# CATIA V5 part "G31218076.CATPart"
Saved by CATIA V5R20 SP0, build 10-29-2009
Part number: G31218076
Revision: 8
Definition: design
Nomenclature: G31218076
Source: made
Description: NOT SPECIFIED
Bounding box of the stored display mesh (mm): x -8 to 76, y -15.5 to 15.5, z -15.5 to 15.5
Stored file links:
  C:\Users\Raffaele\Desktop\3D X SITO CF\BOLEX\23-BUSH REF 312\G31218076.CATPart

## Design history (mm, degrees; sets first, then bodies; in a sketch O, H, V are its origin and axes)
Body1 "MANIFOLD_SOLID_BREP #19379" (main body)
  Solid1: solid without history
Body2 "MANIFOLD_SOLID_BREP #19526"
  Solid2: solid without history
Body3 "MANIFOLD_SOLID_BREP #19673"
  Solid3: solid without history
Body4 "MANIFOLD_SOLID_BREP #19820"
  Solid4: solid without history
Body5 "MANIFOLD_SOLID_BREP #19967"
  Solid5: solid without history
Body6 "MANIFOLD_SOLID_BREP #20116"
  Solid6: solid without history
Body7 "MANIFOLD_SOLID_BREP #20265"
  Solid7: solid without history
Body8 "MANIFOLD_SOLID_BREP #20414"
  Solid8: solid without history
Body9 "MANIFOLD_SOLID_BREP #20563"
  Solid9: solid without history
Body10 "MANIFOLD_SOLID_BREP #20712"
  Solid10: solid without history
Body11 "MANIFOLD_SOLID_BREP #20861"
  Solid11: solid without history
Body12 "MANIFOLD_SOLID_BREP #21010"
  Solid12: solid without history
Body13 "MANIFOLD_SOLID_BREP #21159"
  Solid13: solid without history
Body14 "MANIFOLD_SOLID_BREP #21308"
  Solid14: solid without history
Body15 "MANIFOLD_SOLID_BREP #21457"
  Solid15: solid without history
Body16 "MANIFOLD_SOLID_BREP #21606"
  Solid16: solid without history
Body17 "MANIFOLD_SOLID_BREP #21755"
  Solid17: solid without history
Body18 "MANIFOLD_SOLID_BREP #21904"
  Solid18: solid without history
Body19 "MANIFOLD_SOLID_BREP #22053"
  Solid19: solid without history
Body20 "MANIFOLD_SOLID_BREP #22202"
  Solid20: solid without history
Body21 "MANIFOLD_SOLID_BREP #22351"
  Solid21: solid without history
Body22 "MANIFOLD_SOLID_BREP #22500"
  Solid22: solid without history
Body23 "MANIFOLD_SOLID_BREP #22649"
  Solid23: solid without history
Body24 "MANIFOLD_SOLID_BREP #22798"
  Solid24: solid without history
Body25 "MANIFOLD_SOLID_BREP #22947"
  Solid25: solid without history
Body26 "MANIFOLD_SOLID_BREP #23096"
  Solid26: solid without history
Body27 "MANIFOLD_SOLID_BREP #23245"
  Solid27: solid without history
Body28 "MANIFOLD_SOLID_BREP #23394"
  Solid28: solid without history
Body29 "MANIFOLD_SOLID_BREP #23543"
  Solid29: solid without history
Body30 "MANIFOLD_SOLID_BREP #23692"
  Solid30: solid without history
Body31 "MANIFOLD_SOLID_BREP #23841"
  Solid31: solid without history
Body32 "MANIFOLD_SOLID_BREP #23988"
  Solid32: solid without history
Body33 "MANIFOLD_SOLID_BREP #24135"
  Solid33: solid without history
Body34 "MANIFOLD_SOLID_BREP #24284"
  Solid34: solid without history
Body35 "MANIFOLD_SOLID_BREP #24433"
  Solid35: solid without history
Body36 "MANIFOLD_SOLID_BREP #24582"
  Solid36: solid without history
Body37 "MANIFOLD_SOLID_BREP #24731"
  Solid37: solid without history
Body38 "MANIFOLD_SOLID_BREP #24880"
  Solid38: solid without history
Body39 "MANIFOLD_SOLID_BREP #25029"
  Solid39: solid without history
Body40 "MANIFOLD_SOLID_BREP #25178"
  Solid40: solid without history
Body41 "MANIFOLD_SOLID_BREP #25327"
  Solid41: solid without history
Body42 "MANIFOLD_SOLID_BREP #25476"
  Solid42: solid without history
Body43 "MANIFOLD_SOLID_BREP #25625"
  Solid43: solid without history
Body44 "MANIFOLD_SOLID_BREP #25774"
  Solid44: solid without history
Body45 "MANIFOLD_SOLID_BREP #25923"
  Solid45: solid without history
Body46 "MANIFOLD_SOLID_BREP #26072"
  Solid46: solid without history
Body47 "MANIFOLD_SOLID_BREP #26221"
  Solid47: solid without history
Body48 "MANIFOLD_SOLID_BREP #26370"
  Solid48: solid without history
Body49 "MANIFOLD_SOLID_BREP #26519"
  Solid49: solid without history
Body50 "MANIFOLD_SOLID_BREP #26668"
  Solid50: solid without history
Body51 "MANIFOLD_SOLID_BREP #26817"
  Solid51: solid without history
Body52 "MANIFOLD_SOLID_BREP #26966"
  Solid52: solid without history
Body53 "MANIFOLD_SOLID_BREP #27115"
  Solid53: solid without history
Body54 "MANIFOLD_SOLID_BREP #27264"
  Solid54: solid without history
Body55 "MANIFOLD_SOLID_BREP #27413"
  Solid55: solid without history
Body56 "MANIFOLD_SOLID_BREP #27560"
  Solid56: solid without history
Body57 "MANIFOLD_SOLID_BREP #27707"
  Solid57: solid without history
Body58 "MANIFOLD_SOLID_BREP #27856"
  Solid58: solid without history
Body59 "MANIFOLD_SOLID_BREP #28005"
  Solid59: solid without history
Body60 "MANIFOLD_SOLID_BREP #28154"
  Solid60: solid without history
Body61 "MANIFOLD_SOLID_BREP #28303"
  Solid61: solid without history
Body62 "MANIFOLD_SOLID_BREP #28452"
  Solid62: solid without history
Body63 "MANIFOLD_SOLID_BREP #28601"
  Solid63: solid without history
Body64 "MANIFOLD_SOLID_BREP #28748"
  Solid64: solid without history
Body65 "MANIFOLD_SOLID_BREP #28895"
  Solid65: solid without history
Body66 "MANIFOLD_SOLID_BREP #29044"
  Solid66: solid without history
Body67 "MANIFOLD_SOLID_BREP #29193"
  Solid67: solid without history
Body68 "MANIFOLD_SOLID_BREP #29342"
  Solid68: solid without history
Body69 "MANIFOLD_SOLID_BREP #29491"
  Solid69: solid without history
Body70 "MANIFOLD_SOLID_BREP #29640"
  Solid70: solid without history
Body71 "MANIFOLD_SOLID_BREP #29789"
  Solid71: solid without history
Body72 "MANIFOLD_SOLID_BREP #29938"
  Solid72: solid without history
Body73 "MANIFOLD_SOLID_BREP #30087"
  Solid73: solid without history
Body74 "MANIFOLD_SOLID_BREP #30236"
  Solid74: solid without history
Body75 "MANIFOLD_SOLID_BREP #30385"
  Solid75: solid without history
Body76 "MANIFOLD_SOLID_BREP #30534"
  Solid76: solid without history
Body77 "MANIFOLD_SOLID_BREP #30683"
  Solid77: solid without history
Body78 "MANIFOLD_SOLID_BREP #30832"
  Solid78: solid without history
Body79 "MANIFOLD_SOLID_BREP #30981"
  Solid79: solid without history
Body80 "MANIFOLD_SOLID_BREP #31130"
  Solid80: solid without history
Body81 "MANIFOLD_SOLID_BREP #31279"
  Solid81: solid without history
Body82 "MANIFOLD_SOLID_BREP #31428"
  Solid82: solid without history
Body83 "MANIFOLD_SOLID_BREP #31577"
  Solid83: solid without history
Body84 "MANIFOLD_SOLID_BREP #31726"
  Solid84: solid without history
Body85 "MANIFOLD_SOLID_BREP #31875"
  Solid85: solid without history
Body86 "MANIFOLD_SOLID_BREP #32022"
  Solid86: solid without history
Body87 "MANIFOLD_SOLID_BREP #32169"
  Solid87: solid without history
Body88 "MANIFOLD_SOLID_BREP #32316"
  Solid88: solid without history
Body89 "MANIFOLD_SOLID_BREP #32463"
  Solid89: solid without history
Body90 "MANIFOLD_SOLID_BREP #32612"
  Solid90: solid without history
Body91 "MANIFOLD_SOLID_BREP #32761"
  Solid91: solid without history
Body92 "MANIFOLD_SOLID_BREP #32910"
  Solid92: solid without history
Body93 "MANIFOLD_SOLID_BREP #33059"
  Solid93: solid without history
Body94 "MANIFOLD_SOLID_BREP #33208"
  Solid94: solid without history
Body95 "MANIFOLD_SOLID_BREP #33357"
  Solid95: solid without history
Body96 "MANIFOLD_SOLID_BREP #33506"
  Solid96: solid without history
Body97 "MANIFOLD_SOLID_BREP #33655"
  Solid97: solid without history
Body98 "MANIFOLD_SOLID_BREP #33804"
  Solid98: solid without history
Body99 "MANIFOLD_SOLID_BREP #33953"
  Solid99: solid without history
Body100 "MANIFOLD_SOLID_BREP #34102"
  Solid100: solid without history
Body101 "MANIFOLD_SOLID_BREP #34251"
  Solid101: solid without history
Body102 "MANIFOLD_SOLID_BREP #34400"
  Solid102: solid without history
Body103 "MANIFOLD_SOLID_BREP #34549"
  Solid103: solid without history
Body104 "MANIFOLD_SOLID_BREP #34698"
  Solid104: solid without history
Body105 "MANIFOLD_SOLID_BREP #34847"
  Solid105: solid without history
Body106 "MANIFOLD_SOLID_BREP #34996"
  Solid106: solid without history
Body107 "MANIFOLD_SOLID_BREP #35145"
  Solid107: solid without history
Body108 "MANIFOLD_SOLID_BREP #35294"
  Solid108: solid without history
Body109 "MANIFOLD_SOLID_BREP #35443"
  Solid109: solid without history
Body110 "MANIFOLD_SOLID_BREP #35592"
  Solid110: solid without history
Body111 "MANIFOLD_SOLID_BREP #35741"
  Solid111: solid without history
Body112 "MANIFOLD_SOLID_BREP #35888"
  Solid112: solid without history
Body113 "MANIFOLD_SOLID_BREP #36035"
  Solid113: solid without history
Body114 "MANIFOLD_SOLID_BREP #36184"
  Solid114: solid without history
Body115 "MANIFOLD_SOLID_BREP #36333"
  Solid115: solid without history
Body116 "MANIFOLD_SOLID_BREP #36482"
  Solid116: solid without history
Body117 "MANIFOLD_SOLID_BREP #36631"
  Solid117: solid without history
Body118 "MANIFOLD_SOLID_BREP #36780"
  Solid118: solid without history
Body119 "MANIFOLD_SOLID_BREP #36929"
  Solid119: solid without history
Body120 "MANIFOLD_SOLID_BREP #37078"
  Solid120: solid without history
Body121 "MANIFOLD_SOLID_BREP #37227"
  Solid121: solid without history
Body122 "MANIFOLD_SOLID_BREP #37376"
  Solid122: solid without history
Body123 "MANIFOLD_SOLID_BREP #37525"
  Solid123: solid without history
Body124 "MANIFOLD_SOLID_BREP #37674"
  Solid124: solid without history
Body125 "MANIFOLD_SOLID_BREP #37823"
  Solid125: solid without history
Body126 "MANIFOLD_SOLID_BREP #37972"
  Solid126: solid without history
Body127 "MANIFOLD_SOLID_BREP #38121"
  Solid127: solid without history
Body128 "MANIFOLD_SOLID_BREP #38268"
  Solid128: solid without history
Body129 "MANIFOLD_SOLID_BREP #38415"
  Solid129: solid without history
Body130 "MANIFOLD_SOLID_BREP #38564"
  Solid130: solid without history
Body131 "MANIFOLD_SOLID_BREP #38713"
  Solid131: solid without history
Body132 "MANIFOLD_SOLID_BREP #38862"
  Solid132: solid without history
Body133 "MANIFOLD_SOLID_BREP #39011"
  Solid133: solid without history
Body134 "MANIFOLD_SOLID_BREP #39160"
  Solid134: solid without history
Body135 "MANIFOLD_SOLID_BREP #39309"
  Solid135: solid without history
Body136 "MANIFOLD_SOLID_BREP #39458"
  Solid136: solid without history
Body137 "MANIFOLD_SOLID_BREP #39607"
  Solid137: solid without history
